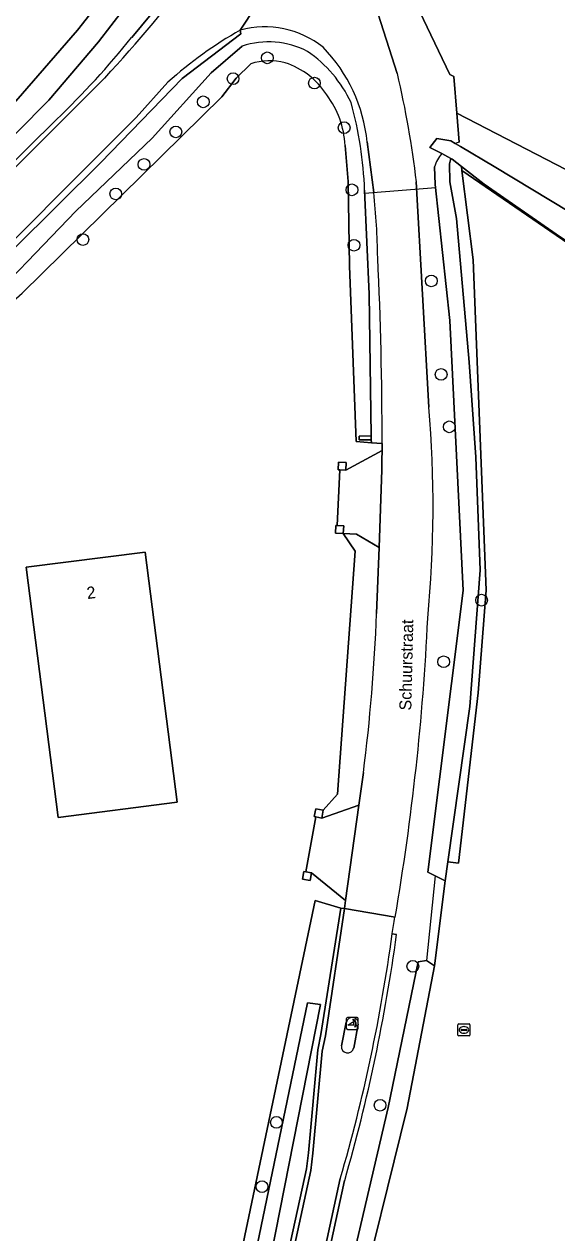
# Model space of a CAD drawing. Extents: x 164494 to 166241, y 382475 to 384495.
# Drawn here: x 165197.8 to 165242.2, y 383771 to 383871.8 of the extents above; entities that cross this region are included whole.
import ezdxf

# ---------------------------------------------------------------- set-up
doc = ezdxf.new("R2010")
doc.units = 0
for name, color, linetype in [('IMGEO_Berm_halfverhard', 7, 'Continuous'), ('IMGEO_Boom', 7, 'Continuous'), ('IMGEO_Bouwland', 7, 'Continuous'), ('IMGEO_Duiker', 7, 'Continuous'), ('IMGEO_Erf', 7, 'Continuous'), ('IMGEO_Groenvoorziening', 7, 'Continuous'), ('IMGEO_Hek', 7, 'Continuous'), ('IMGEO_Loofbos', 7, 'Continuous'), ('IMGEO_Muur', 7, 'Continuous'), ('IMGEO_Openbare_ruimte_label', 7, 'Continuous'), ('IMGEO_Pand', 7, 'Continuous'), ('IMGEO_Pand_nummerreeks', 7, 'Continuous'), ('IMGEO_Poller', 7, 'Continuous'), ('IMGEO_Rijbaan_lokaal_gesloten', 7, 'Continuous'), ('IMGEO_Rijbaan_lokaal_open', 7, 'Continuous'), ('IMGEO_Rioolput', 7, 'Continuous'), ('IMGEO_Verkeerseiland_open', 7, 'Continuous'), ('IMGEO_Voetpad_open', 7, 'Continuous'), ('IMGEO_Waterloop', 7, 'Continuous')]:
    doc.layers.add(name, color=color, linetype=linetype)

msp = doc.modelspace()

# ---------------------------------------------------------------- linework, layer by layer
at = {"layer": 'IMGEO_Berm_halfverhard'}
for points in [[(165208.37, 383872.67), (165206.74, 383870.72)], [(165210.96, 383867.3), (165215.83, 383871.02), (165215.8, 383871.33)], [(165151.31, 383817.47), (165161.16, 383825.98), (165189.28, 383852.13), (165204.49, 383867.34)], [(165209.76, 383866.98), (165207.1, 383864.05), (165191.89, 383848.84), (165163.79, 383822.15), (165154.07, 383813.85)], [(165155.21, 383814.13), (165161.39, 383819.48), (165166.15, 383823.61), (165179.1, 383835.82), (165189.6, 383845.87), (165204.16, 383860.28), (165210.96, 383867.3)], [(165200.47, 383863.87), (165186.12, 383849.72), (165175.19, 383839.32)]]:
    msp.add_lwpolyline(points, dxfattribs=at)
for centre, radius, start, end in [((165124.54, 383941.84), 109.28, 317.0178, 329.8082), ((165233.31, 383840.69), 35.3, 119.7415, 131.8457), ((165149.31, 383916.98), 73.74, 313.9288, 321.1451)]:
    msp.add_arc(centre, radius, start, end, dxfattribs=at)
at = {"layer": 'IMGEO_Boom'}
for centre in [(165218.05, 383869.02), (165215.2, 383867.28), (165221.98, 383866.91), (165212.71, 383865.35), (165210.42, 383862.84), (165224.46, 383863.19), (165207.77, 383860.13), (165205.41, 383857.67), (165225.11, 383858.01), (165202.67, 383853.86), (165225.28, 383853.39), (165231.73, 383850.41), (165232.55, 383842.61), (165233.23, 383838.24), (165235.92, 383823.78), (165232.76, 383818.64), (165230.19, 383793.24), (165227.46, 383781.65), (165218.81, 383780.22), (165217.61, 383774.86)]:
    msp.add_circle(centre, 0.489, dxfattribs=at)
at = {"layer": 'IMGEO_Bouwland'}
for points in [[(165158.01, 383827.73), (165178.91, 383847.63), (165182.01, 383850.58), (165183.14, 383851.66), (165197.08, 383865.4), (165202.22, 383871.34), (165210.02, 383881.29), (165214.6, 383887.84), (165221.57, 383898.87), (165232.71, 383917.65), (165253.51, 383950.72), (165257.18, 383956.47), (165255.58, 383956.1), (165245.66, 383954.08), (165196.93, 383941.72), (165196.92, 383941.72), (165158.09, 383932.3), (165144.84, 383929.35), (165142.48, 383930.92), (165138.05, 383949.06), (165081.65, 383927.93)], [(165229.49, 383875.54), (165233.28, 383867.63), (165233.6, 383867.46), (165233.86, 383864.4), (165243.81, 383859.25), (165247.27, 383856.67), (165301.5, 383816.36), (165301.09, 383815.8), (165300.59, 383815.1), (165304.71, 383811.7), (165305.18, 383812.21), (165305.9, 383813.09), (165308.93, 383810.84), (165309.87, 383813.78), (165323.43, 383873.21)], [(165300.16, 383814.51), (165300.13, 383814.46), (165294.29, 383818.46), (165234.27, 383859.63), (165235.23, 383852.16), (165236.31, 383824.62), (165235.63, 383816.06), (165234, 383801.83), (165233.1, 383801.95), (165232.88, 383800.37), (165232, 383793.29), (165229.71, 383781.42), (165225.36, 383763.73), (165222.75, 383750), (165214.71, 383707.74)]]:
    msp.add_lwpolyline(points, dxfattribs=at)
at = {"layer": 'IMGEO_Duiker'}
for points in [[(165226.15, 383857.73), (165232.12, 383858.21)], [(165232.05, 383800.79), (165231.32, 383793.72)]]:
    msp.add_lwpolyline(points, dxfattribs=at)
at = {"layer": 'IMGEO_Erf'}
for points in [[(165216.67, 383868.52), (165215.46, 383867.31), (165214.25, 383865.78), (165197.6, 383849.39), (165190.2, 383842.41), (165171.67, 383824.21), (165163.5, 383817.22), (165156.8, 383811.47), (165144.65, 383802.77), (165145.85, 383799.61), (165146.55, 383797.78), (165157.89, 383767.91), (165170.64, 383734.86), (165189.95, 383730.66), (165207.26, 383727.36), (165211.82, 383750), (165222.05, 383798.74), (165224.17, 383798.09), (165224.48, 383798.05), (165224.58, 383798.72), (165221.74, 383801.03)], [(165221.74, 383801.03), (165221.63, 383800.4), (165220.99, 383800.51), (165221.1, 383801.14), (165221.26, 383801.11), (165222.09, 383805.71), (165221.96, 383805.73), (165222.09, 383806.37), (165222.7, 383806.25), (165223.9, 383807.6), (165225.39, 383827.88), (165224.38, 383829.34), (165223.73, 383829.38), (165223.77, 383830.02), (165223.89, 383830.01), (165224.1, 383834.65), (165223.97, 383834.65), (165224, 383835.29), (165224.64, 383835.26), (165224.61, 383834.62), (165227.62, 383836.26), (165227.62, 383836.56), (165227.62, 383836.85), (165226.73, 383836.91), (165225.47, 383837.01), (165224.91, 383851.66), (165224.8, 383858.7), (165224.54, 383861.72)]]:
    msp.add_lwpolyline(points, dxfattribs=at)
for points in [[(165224.1, 383834.65), (165224.61, 383834.62), (165224.64, 383835.26), (165224, 383835.29), (165223.97, 383834.65)], [(165223.77, 383830.02), (165223.73, 383829.38), (165224.38, 383829.34), (165224.42, 383829.98), (165223.89, 383830.01)], [(165200.6, 383805.66), (165197.95, 383826.52), (165207.87, 383827.79), (165210.53, 383806.93)], [(165222.09, 383805.71), (165222.61, 383805.61), (165222.7, 383806.25), (165222.09, 383806.37), (165221.96, 383805.73)], [(165221.1, 383801.14), (165220.99, 383800.51), (165221.63, 383800.4), (165221.74, 383801.03), (165221.26, 383801.11)]]:
    msp.add_lwpolyline(points, close=True, dxfattribs=at)
for centre, radius, start, end in [((165218.26, 383863.2), 5.56, 76.6031, 106.6223), ((165217.51, 383862.39), 6.54, 32.7261, 71.8044), ((165216.84, 383861.3), 7.71, 3.0725, 36.8566)]:
    msp.add_arc(centre, radius, start, end, dxfattribs=at)
at = {"layer": 'IMGEO_Groenvoorziening'}
for points in [[(165258.85, 383956.81), (165258.57, 383956.78), (165257.18, 383956.47), (165253.51, 383950.72), (165254.42, 383950.13), (165255.25, 383949.6), (165245.53, 383934.16), (165236.56, 383918.92), (165232.41, 383912.89), (165223.55, 383898.77), (165210.14, 383878.39), (165203.98, 383870.35), (165199.84, 383865.48), (165189.04, 383854.61), (165183.1, 383848.91), (165182.55, 383849.75), (165182.01, 383850.58), (165178.91, 383847.63), (165179.62, 383846.93), (165180.32, 383846.24), (165169.72, 383836.09), (165159.93, 383826.48)], [(165234.06, 383861.99), (165233.86, 383864.4), (165233.6, 383867.46), (165233.28, 383867.63), (165229.49, 383875.54), (165229.15, 383884.65), (165228.21, 383885.28), (165227.86, 383885.74), (165226.38, 383886.89), (165225.96, 383886.89)], [(165227.07, 383873.35), (165228.89, 383867.71)], [(165206.74, 383870.72), (165208.37, 383872.67)], [(165215.8, 383871.33), (165215.83, 383871.02), (165210.96, 383867.3), (165204.16, 383860.28), (165189.6, 383845.87), (165179.1, 383835.82), (165166.15, 383823.61), (165161.39, 383819.48), (165155.21, 383814.13)], [(165193.29, 383847.1), (165202.07, 383856.24), (165208.44, 383862.32), (165213.36, 383867.78), (165215.94, 383869.99)], [(165175.19, 383839.32), (165186.12, 383849.72), (165200.47, 383863.87)], [(165226.94, 383857.78), (165226.38, 383862)], [(165232.6, 383861.03), (165231.61, 383861.54), (165232.2, 383862.28), (165233.36, 383862.09), (165233.73, 383861.87)], [(165207.95, 383667.8), (165208.26, 383669.95), (165209.1, 383675.95), (165209.57, 383680.75), (165210.23, 383683.79), (165210.82, 383688.54), (165211.44, 383695.56), (165212.92, 383706.55), (165221.07, 383750), (165224.06, 383764.09), (165228.12, 383781.47), (165230.62, 383793.62), (165231.32, 383793.72), (165232, 383793.29), (165232.88, 383800.37), (165232.05, 383800.79), (165231.43, 383801.1), (165234.4, 383824.58), (165233.28, 383847.12), (165232.04, 383858.45), (165232, 383859.92)], [(165226.16, 383857.97), (165226.54, 383849.31), (165226.72, 383837.48), (165226.72, 383837.16), (165226.73, 383836.91), (165227.62, 383836.85)], [(165230.48, 383858.67), (165231.52, 383839.89)], [(165227.17, 383822.67), (165227.37, 383828.18), (165225.5, 383829.28), (165224.38, 383829.34), (165225.39, 383827.88), (165223.9, 383807.6), (165222.7, 383806.25), (165222.61, 383805.61), (165225.68, 383806.67), (165226.07, 383809.4)], [(165215.6, 383750), (165216.37, 383753.71), (165221.33, 383776.35), (165221.48, 383777.69), (165222.26, 383786.26), (165222.51, 383787.54), (165224.17, 383798.09), (165222.05, 383798.74), (165211.82, 383750), (165207.26, 383727.36), (165208.3, 383727.11), (165213.05, 383750), (165221.4, 383790.2), (165222.49, 383790.05), (165214.58, 383750), (165210.08, 383727.24), (165206.45, 383702.34)], [(165228.47, 383795.96), (165228.83, 383795.89)], [(165224.5, 383775.37), (165219.61, 383752.9), (165218.99, 383750)]]:
    msp.add_lwpolyline(points, dxfattribs=at)
msp.add_lwpolyline([(165234.24, 383859.96), (165233.47, 383860.57), (165233.36, 383860.63), (165233.24, 383860.19), (165233.27, 383858.67), (165233.82, 383855.62), (165234.9, 383843.63), (165235.44, 383835.72), (165235.8, 383826.28), (165234.93, 383814.91), (165233.1, 383801.95), (165234, 383801.83), (165235.63, 383816.06), (165236.31, 383824.62), (165235.23, 383852.16), (165234.27, 383859.63)], close=True, dxfattribs=at)
for centre, radius, start, end in [((165217.84, 383863.8), 7.8, 51.4425, 105.131), ((165149.31, 383916.98), 73.74, 313.9288, 321.1451), ((165218.15, 383863.29), 7.06, 62.5391, 108.2255), ((165215.48, 383860.85), 10.53, 24.8937, 55.7902), ((165213.28, 383860.71), 13.16, 5.5963, 44.2954), ((165153.74, 383849.85), 77.25, 6.5546, 13.371), ((165195.46, 383856.96), 30.72, 1.8829, 15.7178), ((165234.99, 383858.98), 3.16, 107.244, 113.6396), ((165235, 383859.02), 3.13, 140.0681, 163.1132), ((165160.77, 383851.14), 66.5, 1.0256, 5.7332), ((164929.72, 383837.68), 297.9, 359.8406, 2.8177), ((165136.16, 383831.55), 95.72, 354.4348, 4.9996), ((165075.49, 383828.55), 151.79, 352.7511, 357.7774), ((165026.07, 383832.07), 205.6, 350.2713, 357.2677), ((165077.38, 383823.12), 153.5, 349.81, 350.3273), ((165084.17, 383815.71), 146.02, 343.9626, 352.2005)]:
    msp.add_arc(centre, radius, start, end, dxfattribs=at)
at = {"layer": 'IMGEO_Hek'}
for points in [[(165234.27, 383859.63), (165294.29, 383818.46), (165300.34, 383814.32), (165313.5, 383802.36), (165307.58, 383792.13)], [(165224.1, 383834.65), (165223.89, 383830.01)], [(165224.38, 383829.34), (165225.39, 383827.88), (165223.9, 383807.6), (165222.7, 383806.25)], [(165221.26, 383801.11), (165222.09, 383805.71)]]:
    msp.add_lwpolyline(points, dxfattribs=at)
at = {"layer": 'IMGEO_Loofbos'}
for points in [[(165233.73, 383861.87), (165234.17, 383861.61), (165236.98, 383859.96), (165243.27, 383856.15), (165253.49, 383848.99), (165262.72, 383842.83), (165264.71, 383840.91), (165266.57, 383839.74), (165271.06, 383836.84), (165273.49, 383835.04), (165280.62, 383830.68), (165295.83, 383819.63), (165301.09, 383815.8), (165301.5, 383816.36), (165247.27, 383856.67), (165243.81, 383859.25), (165233.86, 383864.4)], [(165233.86, 383864.4), (165234.06, 383861.99)]]:
    msp.add_lwpolyline(points, dxfattribs=at)
msp.add_lwpolyline([(165292.83, 383819.73), (165283.29, 383826.11), (165270.03, 383835.41), (165259.32, 383842.88), (165249.59, 383849.36), (165242.5, 383854.05), (165236.14, 383858.47), (165234.24, 383859.96), (165234.27, 383859.63), (165294.29, 383818.46), (165300.13, 383814.46), (165300.16, 383814.51), (165294.86, 383818.29)], close=True, dxfattribs=at)
msp.add_arc((165234.99, 383858.98), 3.16, 107.244, 113.6396, dxfattribs=at)
at = {"layer": 'IMGEO_Muur'}
msp.add_lwpolyline([(165226.72, 383837.48), (165225.71, 383837.47), (165225.72, 383837.15), (165226.72, 383837.16)], close=True, dxfattribs=at)
at = {"layer": 'IMGEO_Pand'}
msp.add_lwpolyline([(165200.6, 383805.66), (165210.53, 383806.93), (165207.87, 383827.79), (165197.95, 383826.52)], close=True, dxfattribs=at)
at = {"layer": 'IMGEO_Poller'}
for p, q in [((165224.64, 383788.88), (165224.64, 383788.07)), ((165224.64, 383788.88), (165224.64, 383788.07)), ((165225.54, 383788.98), (165224.74, 383788.98)), ((165225.54, 383788.98), (165224.74, 383788.98)), ((165225.64, 383788.07), (165225.64, 383788.88)), ((165225.64, 383788.07), (165225.64, 383788.88)), ((165224.74, 383787.98), (165225.54, 383787.98)), ((165224.74, 383787.98), (165225.54, 383787.98))]:
    msp.add_line(p, q, dxfattribs=at)
for points in [[(165225.28, 383788.33), (165224.76, 383788.33), (165225.19, 383788.61)], [(165225.32, 383788.71), (165225.31, 383788.63), (165225.18, 383788.84)], [(165225.18, 383788.84), (165225.41, 383788.77), (165225.34, 383788.74)], [(165225.34, 383788.16), (165225.4, 383788.39), (165225.43, 383788.32)], [(165225.47, 383788.3), (165225.54, 383788.29), (165225.34, 383788.16)]]:
    msp.add_lwpolyline(points, dxfattribs=at)
for centre, radius, start, end in [((165224.74, 383788.88), 0.0946, 90, 180), ((165224.74, 383788.88), 0.0946, 90, 180), ((165224.95, 383788.38), 0.332, 351.3247, 42.4854), ((165224.96, 383788.39), 0.476, 351.7527, 41.1691), ((165224.96, 383788.39), 0.516, 349.3569, 42.2912), ((165225.54, 383788.88), 0.0946, 0, 90), ((165225.54, 383788.88), 0.0946, 0, 90), ((165224.74, 383788.07), 0.0946, 180, 270), ((165224.74, 383788.07), 0.0946, 180, 270), ((165225.54, 383788.07), 0.0946, 270, 0), ((165225.54, 383788.07), 0.0946, 270, 0)]:
    msp.add_arc(centre, radius, start, end, dxfattribs=at)
at = {"layer": 'IMGEO_Rijbaan_lokaal_gesloten'}
for points in [[(165217.08, 383873.29), (165215.8, 383871.33)], [(165215.8, 383871.33), (165217.08, 383873.29)], [(165228.89, 383867.71), (165227.07, 383873.35)], [(165204.49, 383867.34), (165189.28, 383852.13), (165161.16, 383825.98), (165151.31, 383817.47)], [(165154.07, 383813.85), (165163.79, 383822.15), (165191.89, 383848.84), (165207.1, 383864.05), (165209.76, 383866.98)], [(165226.38, 383862), (165226.94, 383857.78)], [(165231.52, 383839.89), (165230.48, 383858.67)], [(165227.62, 383836.85), (165227.62, 383836.56), (165227.62, 383836.26), (165227.61, 383835.46), (165227.61, 383834.66), (165227.37, 383828.18), (165227.17, 383822.67)], [(165226.07, 383809.4), (165225.68, 383806.67), (165224.58, 383798.72), (165224.48, 383798.05), (165228.71, 383797.33)], [(165228.71, 383797.33), (165224.48, 383798.05), (165222.9, 383787.45), (165222.63, 383786.15), (165221.84, 383777.65), (165221.69, 383776.22), (165216.75, 383753.58), (165216, 383750)], [(165224.25, 383786.61), (165224.64, 383788.58)], [(165225.64, 383788.41), (165225.26, 383786.42)], [(165218.62, 383750), (165219.24, 383752.97), (165224.14, 383775.53)]]:
    msp.add_lwpolyline(points, dxfattribs=at)
for centre, radius, start, end in [((165124.54, 383941.84), 109.28, 317.0178, 329.8082), ((165233.31, 383840.69), 35.3, 119.7415, 131.8457), ((165217.84, 383863.8), 7.8, 51.4425, 105.131), ((165213.28, 383860.71), 13.16, 5.5963, 44.2954), ((165153.74, 383849.85), 77.25, 6.5546, 13.371), ((165160.77, 383851.14), 66.5, 1.0256, 5.7332), ((164929.72, 383837.68), 297.9, 359.8406, 2.8177), ((165136.16, 383831.55), 95.72, 354.4348, 4.9996), ((165075.49, 383828.55), 151.79, 352.7511, 357.7774), ((165026.07, 383832.07), 205.6, 350.2713, 357.2677), ((165077.38, 383823.12), 153.5, 349.81, 350.3273), ((165088.76, 383814.86), 140.98, 343.7983, 352.2949), ((165225.14, 383788.47), 0.506, 352.096, 167.7503), ((165224.75, 383786.52), 0.511, 170.4275, 348.2505)]:
    msp.add_arc(centre, radius, start, end, dxfattribs=at)
at = {"layer": 'IMGEO_Rijbaan_lokaal_open'}
for points in [[(165216, 383750), (165216.75, 383753.58), (165221.69, 383776.22), (165221.84, 383777.65), (165222.63, 383786.15), (165222.9, 383787.45), (165224.48, 383798.05), (165224.17, 383798.09), (165222.51, 383787.54), (165222.26, 383786.26), (165221.48, 383777.69), (165221.33, 383776.35), (165216.37, 383753.71), (165215.6, 383750)], [(165228.83, 383795.89), (165228.47, 383795.96)], [(165224.14, 383775.53), (165219.24, 383752.97), (165218.62, 383750)], [(165218.99, 383750), (165219.61, 383752.9), (165224.5, 383775.37)]]:
    msp.add_lwpolyline(points, dxfattribs=at)
for centre, radius, start, end in [((165088.76, 383814.86), 140.98, 343.7983, 352.2949), ((165084.17, 383815.71), 146.02, 343.9626, 352.2005)]:
    msp.add_arc(centre, radius, start, end, dxfattribs=at)
at = {"layer": 'IMGEO_Rioolput'}
for p, q in [((165233.95, 383787.5), (165233.95, 383788.36)), ((165234.03, 383788.43), (165234.88, 383788.43)), ((165234.95, 383788.36), (165234.95, 383787.5)), ((165234.88, 383787.43), (165234.03, 383787.43)), ((165234.21, 383787.92), (165234.21, 383787.94)), ((165234.25, 383787.97), (165234.65, 383787.97)), ((165234.65, 383787.89), (165234.25, 383787.89)), ((165234.44, 383788.21), (165234.46, 383788.21)), ((165234.46, 383787.65), (165234.44, 383787.65)), ((165234.69, 383787.94), (165234.69, 383787.92))]:
    msp.add_line(p, q, dxfattribs=at)
for points in [[(165233.95, 383787.5), (165233.95, 383788.36)], [(165234.03, 383788.43), (165234.88, 383788.43)], [(165234.95, 383788.36), (165234.95, 383787.5)], [(165234.88, 383787.43), (165234.03, 383787.43)]]:
    msp.add_lwpolyline(points, dxfattribs=at)
for centre, radius, start, end in [((165234.03, 383788.36), 0.0765, 91.552, 178.448), ((165234.03, 383788.36), 0.0765, 91.552, 178.448), ((165234.88, 383788.36), 0.0765, 1.552, 88.448), ((165234.88, 383788.36), 0.0765, 1.552, 88.448), ((165234.03, 383787.51), 0.0765, 181.552, 268.448), ((165234.03, 383787.51), 0.0765, 181.552, 268.448), ((165234.25, 383787.93), 0.0403, 85.8775, 175.7526), ((165234.25, 383787.92), 0.0366, 178.938, 274.7102), ((165234.66, 383787.94), 0.0386, 1.7309, 96.639), ((165234.65, 383787.93), 0.043, 264.8664, 352.4533), ((165234.88, 383787.51), 0.0765, 271.552, 358.448), ((165234.88, 383787.51), 0.0765, 271.552, 358.448)]:
    msp.add_arc(centre, radius, start, end, dxfattribs=at)
for centre, major_axis, ratio, start_param, end_param in [((165234.44, 383787.93), (-0.387, 0.002), 0.722429, 4.712389, 7.853982), ((165234.46, 383787.93), (-0.39, 0.002), 0.717154, 1.570796, 4.712389)]:
    msp.add_ellipse(centre, major_axis=major_axis, ratio=ratio, start_param=start_param, end_param=end_param, dxfattribs=at)
at = {"layer": 'IMGEO_Verkeerseiland_open'}
for points in [[(165224.64, 383788.58), (165224.25, 383786.61)], [(165225.26, 383786.42), (165225.64, 383788.41)]]:
    msp.add_lwpolyline(points, dxfattribs=at)
for centre, radius, start, end in [((165225.14, 383788.47), 0.506, 352.096, 167.7503), ((165224.75, 383786.52), 0.511, 170.4275, 348.2505)]:
    msp.add_arc(centre, radius, start, end, dxfattribs=at)
at = {"layer": 'IMGEO_Voetpad_open'}
for points in [[(165227.62, 383836.26), (165224.61, 383834.62), (165224.1, 383834.65), (165223.89, 383830.01), (165224.42, 383829.98), (165224.38, 383829.34), (165225.5, 383829.28), (165227.37, 383828.18), (165227.61, 383834.66), (165227.61, 383835.46)], [(165224.58, 383798.72), (165225.68, 383806.67), (165222.61, 383805.61), (165222.09, 383805.71), (165221.26, 383801.11), (165221.74, 383801.03)]]:
    msp.add_lwpolyline(points, close=True, dxfattribs=at)
at = {"layer": 'IMGEO_Waterloop'}
for points in [[(165245.53, 383934.16), (165255.25, 383949.6), (165254.42, 383950.13), (165253.51, 383950.72), (165232.71, 383917.65), (165221.57, 383898.87), (165214.6, 383887.84), (165210.02, 383881.29), (165202.22, 383871.34), (165197.08, 383865.4), (165183.14, 383851.66), (165182.01, 383850.58), (165182.55, 383849.75), (165183.1, 383848.91), (165189.04, 383854.61), (165199.84, 383865.48), (165203.98, 383870.35), (165210.14, 383878.39), (165223.55, 383898.77), (165232.41, 383912.89), (165236.56, 383918.92)], [(165225.36, 383763.73), (165229.71, 383781.42), (165232, 383793.29), (165231.32, 383793.72), (165230.62, 383793.62), (165228.12, 383781.47), (165224.06, 383764.09), (165221.07, 383750), (165212.92, 383706.55), (165211.44, 383695.56), (165210.82, 383688.54), (165210.23, 383683.79), (165209.57, 383680.75), (165209.1, 383675.95), (165208.26, 383669.95), (165207.95, 383667.8), (165209.32, 383667.69), (165209.55, 383669.75), (165209.51, 383671.77), (165210.36, 383676.67), (165214.71, 383707.74), (165222.75, 383750)], [(165200.92, 383671.36), (165201.64, 383671.22), (165202.54, 383671.06), (165204.76, 383684.62), (165205.48, 383694), (165206.45, 383702.34), (165210.08, 383727.24), (165214.58, 383750), (165222.49, 383790.05), (165221.4, 383790.2), (165213.05, 383750), (165208.3, 383727.11), (165205.03, 383703.32), (165203.18, 383687.6), (165202.71, 383682.3), (165201.72, 383675.95), (165201.62, 383674.49)]]:
    msp.add_lwpolyline(points, close=True, dxfattribs=at)
for points in [[(165215.94, 383869.99), (165213.36, 383867.78), (165208.44, 383862.32), (165202.07, 383856.24), (165193.29, 383847.1), (165189.22, 383843.89), (165189.29, 383843.74), (165189.41, 383843.62), (165189.29, 383843.47), (165189.69, 383843.07), (165189.85, 383843.21), (165189.95, 383843.06), (165190.11, 383842.8), (165197.6, 383849.39), (165214.25, 383865.78), (165215.46, 383867.31), (165216.67, 383868.52)], [(165243.27, 383856.15), (165236.98, 383859.96), (165234.17, 383861.61), (165233.73, 383861.87), (165233.36, 383862.09), (165232.2, 383862.28), (165231.61, 383861.54), (165232.6, 383861.03), (165233.36, 383860.63), (165233.47, 383860.57), (165234.24, 383859.96), (165236.14, 383858.47), (165242.5, 383854.05)], [(165224.54, 383861.72), (165224.8, 383858.7), (165224.91, 383851.66), (165225.47, 383837.01), (165226.73, 383836.91), (165226.72, 383837.16), (165225.72, 383837.15), (165225.71, 383837.47), (165226.72, 383837.48), (165226.54, 383849.31), (165226.16, 383857.97)], [(165233.82, 383855.62), (165233.27, 383858.67), (165233.24, 383860.19), (165233.36, 383860.63), (165232.6, 383861.03)], [(165232, 383859.92), (165232.04, 383858.45), (165233.28, 383847.12), (165234.4, 383824.58), (165231.43, 383801.1), (165232.05, 383800.79), (165232.88, 383800.37), (165233.1, 383801.95), (165234.93, 383814.91), (165235.8, 383826.28), (165235.44, 383835.72), (165234.9, 383843.63), (165233.82, 383855.62)]]:
    msp.add_lwpolyline(points, dxfattribs=at)
for centre, radius, start, end in [((165218.15, 383863.29), 7.06, 62.5391, 108.2255), ((165215.48, 383860.85), 10.53, 24.8937, 55.7902), ((165218.26, 383863.2), 5.56, 76.6031, 106.6223), ((165217.51, 383862.39), 6.54, 32.7261, 71.8044), ((165216.84, 383861.3), 7.71, 3.0725, 36.8566), ((165195.46, 383856.96), 30.72, 1.8829, 15.7178), ((165235, 383859.02), 3.13, 140.0681, 163.1132)]:
    msp.add_arc(centre, radius, start, end, dxfattribs=at)

# ---------------------------------------------------------------- texts
at = {"layer": 'IMGEO_Openbare_ruimte_label'}
msp.add_text('Schuurstraat', height=1, rotation=88.6824, dxfattribs=at).set_placement((165230.06, 383814.57))
at = {"layer": 'IMGEO_Pand_nummerreeks'}
msp.add_text('2', height=1, rotation=7.3302, dxfattribs=at).set_placement((165203.05, 383823.87))

doc.saveas('drawing.dxf')
